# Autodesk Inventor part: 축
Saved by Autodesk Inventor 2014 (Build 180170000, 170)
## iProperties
Created: 2026-04
Part Number: 축
Material: 일반
Document SubType Name: Modeling
Designer: dg
Density: 1 g/cm^3
Appearance: 기본값
Author: dg
Author: jhkim
Creation Date: 2026-03-26
Sending System: Autodesk Inventor 2026
Preprocessor: ST-DEVELOPER v20.1
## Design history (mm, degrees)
node "축1"
node "솔리드1"
node "기준1"
